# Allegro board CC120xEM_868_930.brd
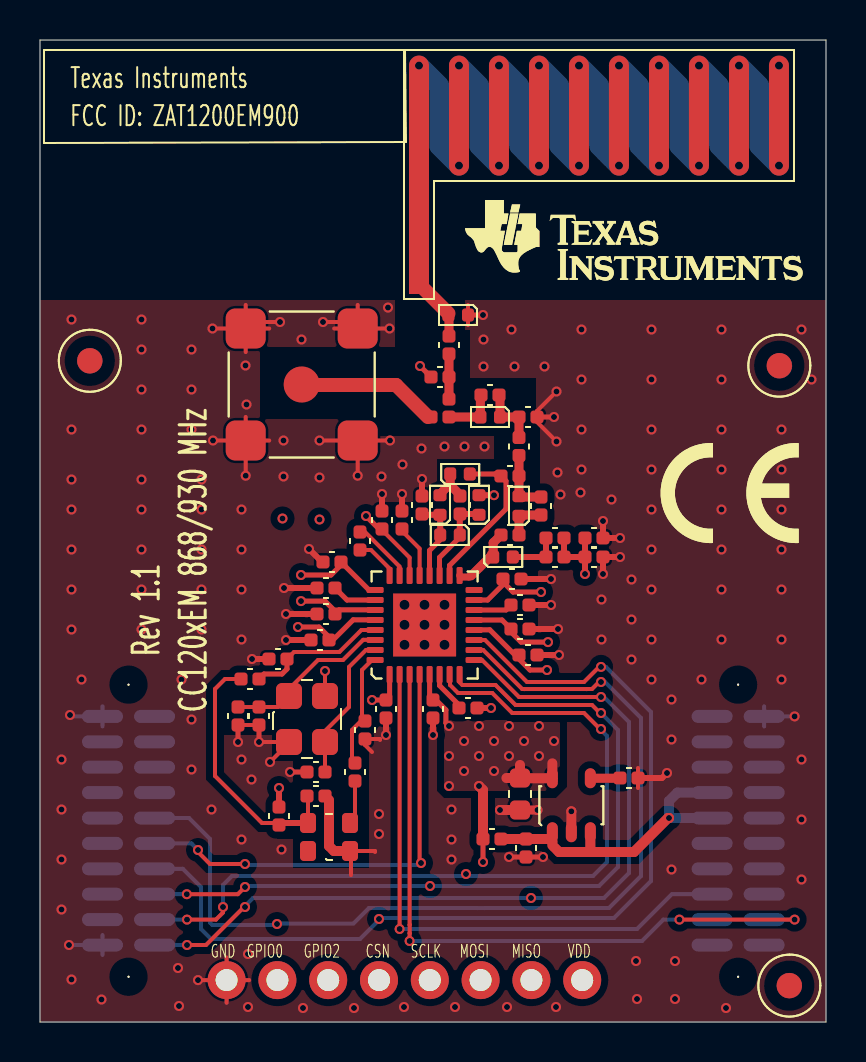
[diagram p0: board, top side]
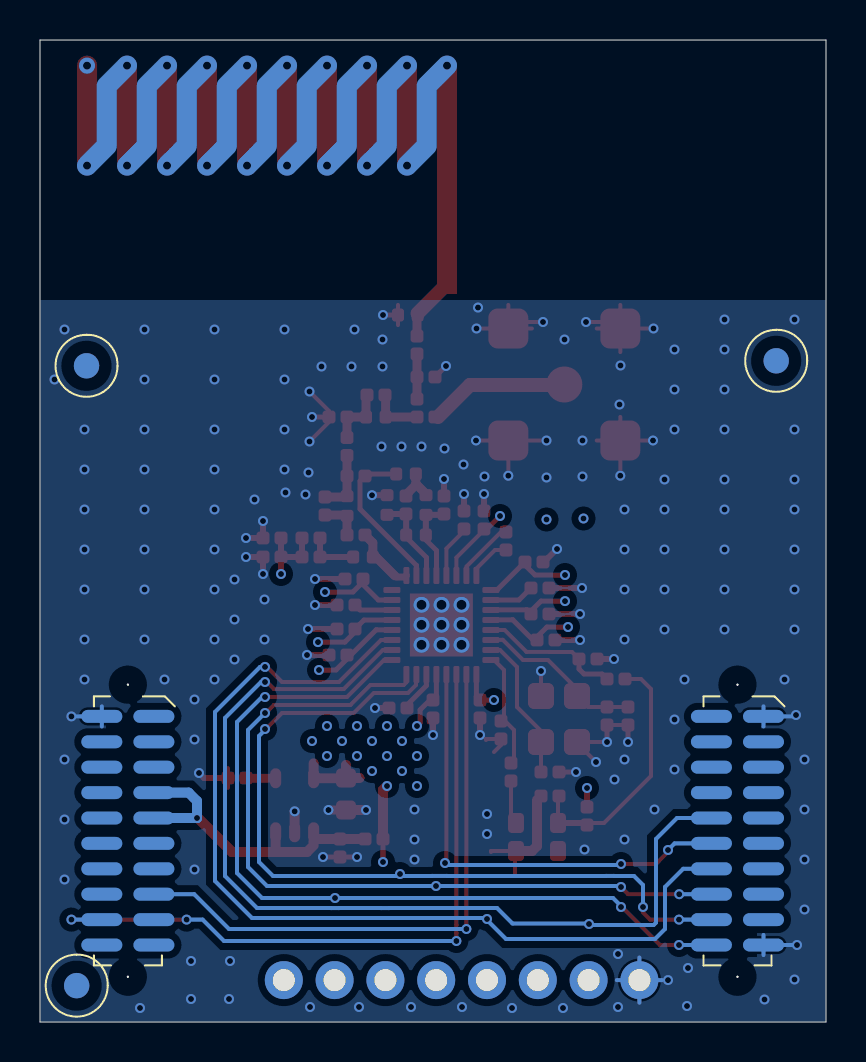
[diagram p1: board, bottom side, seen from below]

Outline 39.3 x 49.1 mm; copper layers: TOP, L2, L3, BOTTOM. Coordinates in mm from the lower left corner of the outline.
Outline path: 0,49.1 0,0 39.3,0 39.3,49.1 0,49.1

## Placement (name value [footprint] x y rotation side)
A1  ANTENNA  [ANTENNA868_915MHZ]  18.95 36.9 0 top
ANT1  DNM_0402  [CAPC1005X60N]  20.45 32.25 180 top
ANT2  1pF  [CAPC1005X60N]  20.45 33.4 90 top
ANT3  12nH  [IND_0402CSAN]  21.4 35.35 180 top
C11  47nF  [CAPC1005X60N]  17.3 16.1 270 top
C12  DNM_0402  [CAPC1005X60N]  24.3 9.15 270 top
C41  DNM_0402  [CAPC1005X60N]  29 12.2 0 top
C51  47nF  [CAPC1005X60N]  19.65 16.1 270 top
C52  2.2uF  [CAPC1608X90N]  24 12.2 270 top
C61  220nF  [CAPC1005X60N]  20.95 15.7 0 top
C121  47nF  [CAPC1005X60N]  24.85 18.35 180 top
C131  47nF  [CAPC1005X60N]  23.55 19.65 0 top
C151  47nF  [CAPC1005X60N]  23.15 22.15 0 top
C171  10nF  [CAPC1005X60N]  27.25 24.2 0 top
C172  100pF  [CAPC1005X60N]  27.25 23.25 0 top
C173  33pF  [CAPC1005X60N]  26.2 24.2 180 top
C174  15pF  [CAPC1005X60N]  23.05 24.35 0 top
C175  3pF  [CAPC1005X60N]  23.95 30.25 0 top
C176  1pF  [CAPC1005X60N]  25.05 25.35 90 top
C177  DNM_0402  [CAPC1005X60N]  22.95 31.35 180 top
C181  2.2pF  [CAPC1005X60N]  23.05 27.3 0 top
C191  3.3pF  [CAPC1005X60N]  21 25.4 90 top
C201  3.3pF  [CAPC1005X60N]  19.1 25.4 90 top
C211  10nF  [CAPC1005X60N]  18.1 24.65 90 top
C221  47nF  [CAPC1005X60N]  17.1 24.65 90 top
C231  1.5nF  [CAPC1005X60N]  16 23.6 90 top
C251  47nF  [CAPC1005X60N]  15.05 23 180 top
C261  47nF  [CAPC1005X60N]  14.75 21.7 180 top
C271  47nF  [CAPC1005X60N]  14.75 20.4 180 top
C281  47nF  [CAPC1005X60N]  14.45 19.1 180 top
C291  47nF  [CAPC1005X60N]  12.35 18.15 180 top
C301  15pF  [CAPC1005X60N]  10.95 15.75 270 top
C302  DNM_0402  [CAPC1005X60N]  9.9 15.75 270 top
C311  15pF  [CAPC1005X60N]  14.25 12.5 180 top
C321  DNM  [CAPC1005X60N]  14.25 11.3 180 top
C322  DNM  [CAPC1005X60N]  15.75 12.05 90 top
FIDU1  FIDU_1.27mm  [FID127X142]  37.47 1.82 0 top
FIDU2  FIDU_1.27mm  [FID127X142]  2.49 33.06 0 top
FIDU3  FIDU_1.27mm  [FID127X142]  36.97 32.81 0 top
FIDU4  FIDU_1.27mm  [FID127X142]  36.98 32.81 180 bottom
FIDU5  FIDU_1.27mm  [FID127X142]  37.47 1.82 180 bottom
FIDU6  FIDU_1.27mm  [FID127X142]  2.49 33.06 180 bottom
L1  BLM15HG102SN1  [INDC1005X60N]  23.05 9.15 180 top
L171  10nH  [IND_0402CSAN]  22.66 23.25 0 top
L172  7.5nH  [IND_0402CSAN]  23.95 25.31 90 top
L173  18nH  [INDC1005X60N]  23.95 28.32 90 top
L174  12nH  [IND_0402CSAN]  23 30.25 180 top
L191  15nH  [IND_0402CSAN]  20.99 24.35 180 top
L192  12nH  [IND_0402CSAN]  21.95 25.36 90 top
L193  12nH  [IND_0402CSAN]  20.51 27.4 0 top
L201  12nH  [IND_0402CSAN]  20 25.36 90 top
NOREF  -  []  -80.15 -110.9 0 top
P1  SFM-110-02-S-D-A-K-TR  [SAMTEC_SFM11002AN]  3.12 15.28 0 bottom
P2  SFM-110-02-S-D-A-K-TR  [SAMTEC_SFM11002AN]  33.61 15.28 0 bottom
P3  SMA-10V21-TGG  [HUSTSAN_SMA10V21TGGAN]  13.08 31.88 0 top
P4  CONN_8  [CON_1X8PAD_T1900CIR1100]  9.33 2.09 0 top
R12  0  [RESC1005X40N]  16.25 15.05 270 top
R141  56k  [RESC1005X40N]  23.55 20.85 0 top
R171  10  [RESC1005X40N]  25.3 23.25 0 top
R181  0  [RESC1005X40AN]  20.45 30.25 180 top
R321  DNM  [RESC1005X40N]  10.95 17.15 180 top
R322  DNM  [RESC1005X40N]  11.95 10.75 270 top
U2  TPS79330  [SOT95P280X145-5N]  25.62 9.49 0 top
U3  CC120xRHB  [QFNFC50P500X500X100-33BN]  17.48 17.38 0 top
UNK#REFDES  -  []  22.25 41.1 0 top
UNK#REFDES#2  -  []  33.65 23.95 0 top
X1  40MHz  [OSCCC250X320X80-4N]  12.45 16.3 270 top
X2  TG-5021CG  [OSCCC200X250X90-4BN]  13.4 8.55 0 top

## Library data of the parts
A1 = ANTENNA
ANT1 ANT2 C11 C12 C41 C51 C61 C121 C131 C151 C171 C172 C174-C177 C181 C191 C201 C211 C221 C231 C251 C261 C271 C281 C291 C301 C302 C311 = CAPACITOR: alternate symbols: (CAPC1005X60L,CAPC1005X60M)
ANT3 L171 L172 L174 L192 L193 L201 = INDUCTOR: alternate symbols: (IND_0402CSAM,IND_0402CSAL)
C52 = CAPACITOR: alternate symbols: (CAPC1608X90L,CAPC1608X90M)
C173 = CAPACITOR: alternate symbols: (CAPC1005X60M,CAPC1005X60L)
C321 C322 = CAPACITOR
FIDU1-FIDU6 = FIDMARK
L1 L191 = INDUCTOR
L173 = INDUCTOR: alternate symbols: (INDC1005X60L,INDC1005X60M)
P1 P2 = CONN_HEADER_2X10_P_S
P3 = CONN_COAX_1+4
P4 = CONN_HEADER_0
R12 R141 R321 R322 = RESISTOR
R171 = RESISTOR: alternate symbols: (RESC1005X40L,RESC1005X40M)
R181 = RESISTOR_3PORTS: alternate symbols: (RESC1005X40AL,RESC1005X40AM,RESC1005X40BL,RESC1005X40BM)
U2 = IC_PM_TPS79930_SOT5_0
U3 = IC_RF_CC1120_QFN32: alternate symbols: (QFNFC50P500X500X100-33BL,QFNFC50P500X500X100-33BM)
X1 = XTAL_4PIN_S: alternate symbols: (OSCCC250X320X80-4L,OSCCC250X320X80-4M)
X2 = XTAL_TG-5021CG

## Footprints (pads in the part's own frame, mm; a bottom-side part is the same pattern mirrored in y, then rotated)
ANTENNA868_915MHZ
  rect 1x1 smd: 1(0,0)
CAPC1005X60N
  custom 0.16x0.16 smd: 1(0,0) 2(0.9,0)
CAPC1608X90N
  custom 0.237x0.237 smd: 1(0,0) 2(1.6,0)
CON_1X8PAD_T1900CIR1100
  round 1.9 hole 1.1: 1(0,0) 2(2.54,0) 3(5.08,0) 4(7.62,0) 5(10.16,0) 6(12.7,0) 7(15.24,0) 8(17.78,0)
FID127X142
  round 1.27 smd: 1(0,0)
HUSTSAN_SMA10V21TGGAN
  round 1.8 smd: 1(0,0)
  custom 0.5x0.5 smd: 2(-2.8,-2.8) 3(2.8,-2.8) 4(2.8,2.8) 5(-2.8,2.8)
IND_0402CSAN
  custom 0.15x0.15 smd: 1(0,0) 2(0.98,0)
INDC1005X60N
  custom 0.16x0.16 smd: 1(0,0) 2(0.9,0)
OSCCC200X250X90-4BN
  custom 0.199x0.199 smd: 1(0,0) 2(2.1,0) 3(2.1,1.4) 4(0,1.4)
OSCCC250X320X80-4N
  custom 0.325x0.325 smd: 1(0,0) 2(2.3,0) 3(2.3,1.8) 4(0,1.8)
QFNFC50P500X500X100-33BN
  custom 0.075x0.075 smd: 1(0,0) 2(0.5,0) 3(1,0) 4(1.5,0) 5(2,0) 6(2.5,0) 7(3,0) 8(3.5,0) 9(4.225,0.725) 10(4.225,1.225) 11(4.225,1.725) 12(4.225,2.225) 13(4.225,2.725) 14(4.225,3.225) 15(4.225,3.725) 16(4.225,4.225) 17(3.5,4.95) 18(3,4.95) 19(2.5,4.95) 20(2,4.95) 21(1.5,4.95) 22(1,4.95) 23(0.5,4.95) 24(0,4.95) 25(-0.725,4.225) 26(-0.725,3.725) 27(-0.725,3.225) 28(-0.725,2.725) 29(-0.725,2.225) 30(-0.725,1.725) 31(-0.725,1.225) 32(-0.725,0.725)
  rect 3.15x3.15 smd: 33(1.75,2.475)
RESC1005X40AN
  custom 0.16x0.16 smd: 1(0,-0.9) 2(0,0) 3(0.9,0)
RESC1005X40N
  custom 0.16x0.16 smd: 1(0,0) 2(0.9,0)
SAMTEC_SFM11002AN
  round 0.1 hole 1.5 unplated: (1.302,-1.587) (1.302,13.018)
  oval 2.05x0.65 smd: 1(0,0) 2(2.603,0) 3(0,1.27) 4(2.603,1.27) 5(0,2.54) 6(2.603,2.54) 7(0,3.81) 8(2.603,3.81) 9(0,5.08) 10(2.603,5.08) 11(0,6.35) 12(2.603,6.35) 13(0,7.62) 14(2.603,7.62) 15(0,8.89) 16(2.603,8.89) 17(0,10.16) 18(2.603,10.16) 19(0,11.43) 20(2.603,11.43)
SOT95P280X145-5N
  oval 0.55x1 smd: 1(0,0) 2(0.95,0) 3(1.9,0) 4(1.9,2.7) 5(0,2.7)

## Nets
3V3A: C12.1 L1.1 P2.7 P2.9 U2.1(IN) U2.3(EN)
GND: ANT1.2 ANT3.1 C11.2 C12.2 C41.2 C51.2 C52.2 C61.2 C121.1 C131.2 C151.2 C171.2 C172.2 C175.2 C201.2 C211.2 C221.2 C251.2 C261.2 C271.2 C281.2 C291.2 C301.2 C302.2 C311.2 C321.1 L192.2 P1.1 P1.19 P2.2 P3.2 P3.3 P3.4 P3.5 P4.1 R12.2 R141.2 U2.2(GND) U3.33(EGP) X1.2 X1.4 X2.2(GND)
VDD_REG: C11.1 C51.1 C52.1 C121.2 C131.1 C151.1 C171.1 C172.1 C173.1 C221.1 C251.1 C271.1 C281.1 L1.2 P4.8 R171.2 R322.1 U2.5(OUT) U3.1(VDD_GUARD) U3.5(DVDD#5) U3.12(DVDD#12) U3.13(AVDD_IF) U3.15(AVDD_RF) U3.22(AVDD_SYNTH1) U3.25(AVDD_PFD_CHP) U3.27(AVDD_SYNTH2) U3.28(AVDD_XOSC)
CSN: P1.14 P4.4 U3.11(CS_N)
DCPL_XOSC: C291.1 R321.1 U3.29(DCPL_XOSC)
GPIO0: P1.10 P4.2 U3.10(GPIO0)
GPIO2: P1.12 P4.3 U3.4(GPIO2)
GPIO3: P2.18 U3.3(GPIO3)
MISO: P1.20 P4.7 U3.9(SO(GPIO1))
MOSI: P1.18 P4.6 U3.7(SI)
RESET: P2.15 U3.2(RESET_N)
SCLK: P1.16 P4.5 U3.8(SCLK)
N02751: C41.1 U2.4(NR)
N03028: C61.1 U3.6(DCPL)
N03080: C211.1 U3.21(DCPL_VCO)
N03171: C261.1 U3.26(DCPL_PFD_CHP)
N03297: C231.2 U3.23(LPF0)
N03301: C231.1 U3.24(LPF1)
N03775: C301.1 C302.1 U3.30(XOSC_Q1) X1.1
N03827: C311.1 U3.31(XOSC_X2) X1.3
N03987: C322.1 X2.3(OUT)
N04005: C322.2 R12.1 U3.32(EXT_OSC)
N04250: C321.2 R321.2 R322.2 X2.4(VCC)
N04524: R141.1 U3.14(RBIAS)
N06943: C191.1 L191.1 L192.1 U3.19(LNA_P)
N06950: C201.1 L191.2 L201.1 U3.20(LNA_N)
N06973: C191.2 L193.1 L201.2
N07362: C181.1 L193.2 U3.18(TRX_SW)
N07471: C174.1 L171.1 U3.17(PA)
N07475: C174.2 C176.1 L172.1
N07485: C176.2 C181.2 L172.2 L173.1
N07738: C175.1 C177.1 L173.2 L174.1
N07781: C177.2 L174.2 R181.2
N08395: C173.2 L171.2 R171.1
N35337: ANT1.1 ANT2.1 R181.1
N35679: A1.1(FEED/GND_1) ANT2.2 ANT3.2
N41911: P3.1 R181.3

Pads without a net: FIDU1 1; FIDU2 1; FIDU3 1; FIDU4 1; FIDU5 1; FIDU6 1; P1 2 3 4 5 6 7 8 9 11 13 15 17; P2 1 3 4 5 6 8 10 11 12 13 14 16 17 19 20; U3 16; X2 1

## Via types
v1: diameter 0.8, hole 0.4, TOP to BOTTOM, 19 vias
v2: diameter 0.5, hole 0.3, TOP to BOTTOM, 229 vias
v3: diameter 0.8, hole 0.5, TOP to BOTTOM, 9 vias

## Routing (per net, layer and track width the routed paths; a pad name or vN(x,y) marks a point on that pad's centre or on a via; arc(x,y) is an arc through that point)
3V3A: length 16.3
  TOP w0.2: 25.62,8.83 25.62,9 ; 27.52,8.52 27.5,8.5
  TOP w0.5: U2.3 27.52,8.52 ; L1.1 C12.1 25.47,9.15 25.62,9 U2.1 ; v2(31.45,10.2) 31.4,10.2 29.7,8.5 25.95,8.5 25.62,8.83
  BOTTOM w0.5: P2.9 v2(31.45,10.2) 31.45,11.05 31.87,11.47 P2.7
GND: length 100.1
  TOP w0.2: P4.1 9.33,3.22 ; P4.1 v2(7.9,2.09) ; P4.1 10.46,2.09 ; P4.1 9.33,0.97 ; 15.88,34.67 15.88,35.85 ; 15.88,34.67 15.56,35 v2(14.15,35) ; 15.88,34.67 14.71,34.67 ; 15.88,34.67 v2(17.47,34.67) ; 16.75,8.5 16.75,8.55 15.55,8.55 ; 29.9,11.7 C41.2 29.9,12.7 ; P3.2 10.29,30.25 ; P3.2 v2(8.65,29.07) ; P3.2 11.46,29.07 ; P3.2 v2(10.29,27.31) ; 15.88,29.07 v2(15.88,27.31) ; 15.88,29.07 v2(17.5,29.07) ; 15.88,29.07 v2(13.97,29.07) ; 21.4,35.85 ANT3.1 21.4,34.85 ; v2(25.82,31.52) 24.85,30.55 C175.2 24.85,30 v2(25.82,29.02) ; P3.5 11.46,34.67 ; P3.5 10.29,33.5 ; P3.5 10.61,35 v2(12,35) ; P3.5 v2(8.62,34.67) ; P3.5 10.29,35.85 ; 16.6,13.5 16.25,13.85 R12.2 17,14.15 17,14.1 ; v2(10.95,14) X1.2 12.45,13.95 v2(11.5,13) ; 15.55,8.55 15.55,7.35 ; 15.55,8.55 X2.2 ; X1.4 v2(14.25,17.55) ; C302.2 C301.2
  TOP w0.25: C321.1 14.45,11.1 ; C311.2 v2(12.5,12.5) ; C175.2 v2(25.7,30.25) ; ANT3.1 v2(22.15,35.35) ; C302.2 v2(9.9,14) ; v2(23.45,8.25) C12.2 v2(25.15,8.25) ; ANT1.2 v2(19,32.8) ; C301.2 v2(10.95,14)
  TOP w0.3: C281.2 v2(12.3,19.1) ; C221.2 v2(17.1,26.4) ; C211.2 v2(18.1,26.4) ; R141.2 v2(25.55,20.85) ; C251.2 14.1,23 v2(13.45,23.65) ; C271.2 v2(12.3,20.4) ; L192.2 v2(22.7,26.34) ; v2(31.35,12.45) 31.1,12.2 C41.2 ; v2(29,24.2) C171.2 v2(28.15,25.05) ; C61.2 v2(22.55,15.7) ; C11.2 v2(17.3,14.35) ; v2(29,23.25) C172.2 v2(28.15,22.4) ; C261.2 v2(12.2,21.7) ; C131.2 v2(25.9,19.65) ; C201.2 v2(19.1,27.15) ; C291.2 v2(10.6,18.15) ; C121.1 v2(25.95,18.35) ; C151.2 v2(25.55,22.15) ; C51.2 v2(19.65,14.35)
  TOP w0.45: C52.2 v2(24.88,10.6)
  TOP w0.5: U2.2 v2(26.57,10.53) ; C52.2 v2(23,10.6) ; 14.45,11.1 14.45,8.8 14.7,8.55 X2.2
  L2 w0.2: 8.2,2.09 P4.1 ; P4.1 9.33,0.97 ; P4.1 10.46,2.09 ; P4.1 9.33,3.22
  L3 w0.2: 8.2,2.09 P4.1 ; P4.1 9.33,0.97 ; P4.1 10.46,2.09 ; P4.1 9.33,3.22
  BOTTOM w0.2: P1.19 v2(1.45,3.85) ; P1.19 3.12,3.35 ; P1.19 3.12,4.35 ; 36.21,14.78 P2.2 ; P2.2 36.21,15.78 ; P2.2 v2(37.73,15.28) ; 8.2,2.09 P4.1 ; P4.1 9.33,0.97 ; P4.1 10.46,2.09 ; P4.1 9.33,3.22 ; 3.12,14.78 P1.1 ; P1.1 3.12,15.78 ; P1.1 1.57,15.28 v2(1.5,15.35)
  vias: v2(1.07,13.12) v2(1.07,10.62) v2(1.07,8.12) v2(1.07,5.62) v2(1.57,35.12) v2(1.57,29.62) v2(1.57,27.12) v2(1.57,25.62) v2(1.57,23.62) v2(1.57,21.62) v2(1.57,19.62) v2(1.57,2.12) v2(2.08,17.12) v2(3.08,1.12) v2(5.08,35.12) v2(5.08,33.62) v2(5.08,31.62) v2(5.08,29.62) v2(5.08,27.12) v2(5.08,25.62) v2(5.08,23.62) v2(5.08,21.62) v2(5.08,19.62) v2(6.9,2.7) v2(6.95,0.8) v2(7.08,17.12) v2(7.58,33.62) v2(7.58,31.62) v2(7.58,29.62) v2(7.58,15.12) v2(7.58,12.62) v2(8.07,27.12) v2(8.07,25.62) v2(8.07,23.62) v2(8.07,21.62) v2(8.07,19.62) v2(8.57,10.62) v2(10.07,25.62) v2(10.07,23.62) v2(10.07,21.62) v2(10.07,19.12) v2(10.07,13.12) v2(10.07,9.12) v2(10.27,32.82) v2(10.32,30.88) v2(10.4,3.4) v2(10.4,0.75) v2(10.57,12.12) v2(12.07,8.62) v2(12.17,29.07) v2(12.17,27.27) v2(13.07,34.12) v2(13.15,0.7) v2(13.97,27.22) v2(15.7,0.7) v2(16.95,10.4) v2(16.95,9.4) v2(17.07,27.27) v2(17.4,35.72) v2(18.12,27.88) v2(18.2,0.75) v2(19.07,28.67) v2(20.22,28.77) v2(20.57,10.62) v2(20.57,9.12) v2(20.57,8.12) v2(20.75,0.75) v2(21.22,28.77) v2(22.18,34.12) v2(22.18,32.77) v2(22.22,28.77) v2(23.35,0.75) v2(23.57,34.62) v2(23.72,32.77) v2(25.22,32.77) v2(25.88,27.47) v2(25.8,0.75) v2(26.02,26.38) v2(27.07,34.62) v2(27.07,32.12) v2(27.07,29.62) v2(27.07,27.62) v2(27.02,26.47) v2(28.07,21.12) v2(28.07,19.12) v2(28.57,26.12) v2(29.57,22.12) v2(29.57,20.12) v2(29.57,18.12) v2(29.8,3.05) v2(29.85,1.15) v2(30.57,34.62) v2(30.57,32.12) v2(30.57,29.62) v2(30.57,27.62) v2(30.57,25.62) v2(30.57,23.62) v2(30.57,21.62) v2(30.57,19.12) v2(30.57,17.12) v2(31.57,16.12) v2(31.57,14.12) v2(31.57,7.62) v2(31.75,3.05) v2(31.75,1.15) v2(33.08,17.12) v2(34.08,34.62) v2(34.08,32.12) v2(34.08,29.62) v2(34.08,27.62) v2(34.08,25.62) v2(34.08,23.62) v2(34.08,21.62) v2(34.08,19.12) v2(34.3,0.7) v2(37.08,29.62) v2(37.08,27.62) v2(37.08,25.62) v2(37.08,23.62) v2(37.08,21.62) v2(37.08,19.12) v2(37.08,17.12) v2(38.08,34.62) v2(38.08,13.12) v2(38.08,10.12) v2(38.08,7.12) v2(38.58,32.12) v3(18.22,20.86) v3(18.22,19.86) v3(18.22,18.86) v3(19.22,20.86) v3(19.22,19.86) v3(19.22,18.86) v3(20.22,20.86) v3(20.22,19.86) v3(20.22,18.86)
VDD_REG: length 56.7
  TOP w0.2: 16.75,20.61 U3.27 ; 17.48,16.28 17.47,16.27 ; U3.22 18.48,23.22 17.1,24.6 C221.1
  TOP w0.25: v2(12.9,19.75) 13.95,19.75 14.45,19.25 C281.1 14.65,19.1 15.66,20.11 16.75,20.11 U3.28 ; U3.13 23.1,20.1 C131.1 ; U3.25 16.45,21.6 C251.1 15.05,22.85 14.55,22.35 v2(13.05,22.35) ; C131.1 23.55,19.5 24.05,18.99 v2(25.4,18.99) ; C131.1 23.5,19.65 ; v2(22.15,8) L1.2 ; U3.1 17.48,16.28 ; U3.15 22.38,21.1 23.15,21.87 23.15,22 ; U3.12 21.71,19.61 22.49,19.61 23.75,18.35 C121.2 23.95,18.15 24.5,17.6 v2(25.35,17.6) ; U3.5 19.48,16.27 C51.1 19.8,16.1 20.29,15.61 20.29,14.96 v2(20.45,14.8) ; 16.75,20.61 14.96,20.61 C271.1 14.75,20.54 14.25,21.04 v2(13.05,21.04) ; 23.15,22 C151.1 ; 23.15,22 23.65,21.5 v2(25.05,21.5) ; v2(16.6,16.1) C11.1 17.47,16.27 ; v2(16.3,25.3) 16.95,24.65 C221.1
  TOP w0.3: C172.1 C171.1 ; C172.1 v2(27.25,22.4) ; C172.1 R171.2 C173.1 ; R322.1 v2(11.95,11.7)
  TOP w0.5: C52.1 23.32,12.2 ; C52.1 24.01,12.19 U2.5 25.62,12.93 ; C52.1 24,12.85 ; L1.2 22.15,11.6 v2(21.95,11.8)
  L3 w0.25: P4.8 27.11,4.59 24.4,7.3 22.85,7.3 v2(22.15,8)
  vias: v2(12.12,25.17) v2(13.97,25.12) v2(20.45,13.3) v2(20.45,11.8) v2(21.2,14.05) v2(21.2,12.55) v2(21.95,14.8) v2(21.95,13.3) v2(22.7,14.05) v2(22.7,12.55) v2(23.45,14.8) v2(23.45,13.3) v2(24.2,14.05) v2(24.95,14.8) v2(24.95,13.3) v2(25.7,14.05)
CSN: length 51.2
  TOP w0.2: v2(28.05,17.75) 27.95,17.75 27.2,17 24.35,17 22.25,19.1 U3.11
  L3 w0.2: P4.4 v2(16.95,5.15)
  BOTTOM w0.2: v2(28.05,17.75) 28.05,17.75 28.3,17.75 30.55,15.5 30.55,7.05 28.7,5.2 17,5.2 v2(16.95,5.15) 16.9,5.1 16.9,5.05 16,4.15 8.55,4.15 8.05,4.65 8.05,6.75 7.14,7.66 P1.14
DCPL_XOSC: length 7.1
  TOP w0.2: C291.1 12.7,18.5 13.8,18.5 13.8,18.5 14.97,18.5 16.07,19.6 U3.29
  TOP w0.25: C291.1 12.35,17.65 12.1,17.4 11.2,17.4 R321.1
GPIO0: length 50.9
  TOP w0.2: v2(28.05,17) 27.95,17 27.6,16.65 27.35,16.65 27.35,16.65 24.2,16.65 24.2,16.65 24.11,16.65 22.16,18.6 U3.10
  L3 w0.2: P4.2 11.87,4.88 v2(11.85,4.9)
  BOTTOM w0.2: P1.10 7.45,10.2 8.5,9.15 8.5,4.97 8.62,4.85 11.8,4.85 v2(11.85,4.9) 11.77,4.9 11.8,4.93 15.67,4.93 16.45,5.7 21.84,5.7 21.84,5.7 22.26,5.7 22.26,5.7 24.34,5.7 24.34,5.7 24.76,5.7 24.76,5.7 28.45,5.7 30.05,7.3 30.05,15.2 28.25,17 v2(28.05,17)
GPIO2: length 30.9
  TOP w0.2: v2(19.05,7.95) 18.98,8.02 U3.4 ; v2(10.25,7.9) 8.5,7.9 7.9,8.5 v2(7.9,8.6)
  L3 w0.2: v2(10.25,7.9) 10.4,7.9 14.41,3.89 P4.3
  BOTTOM w0.2: v2(10.25,7.9) 10.3,7.85 18.95,7.85 v2(19.05,7.95) ; P1.12 7.57,8.93 v2(7.9,8.6)
GPIO3: length 34.5
  TOP w0.2: v2(18.48,4.05) 18.48,4.44 18.48,4.44 18.48,4.86 18.48,4.86 U3.3 ; v2(31.97,5.12) v2(37.73,5.12)
  BOTTOM w0.2: v2(31.97,5.12) 31.17,5.12 30.1,4.05 v2(18.48,4.05) ; v2(37.73,5.12) P2.18
MISO: length 45.9
  TOP w0.2: v2(28.05,16.25) 23.95,16.25 22.1,18.1 U3.9 ; v2(7.35,3.85) 8.3,3.85 10.2,5.75 v2(10.25,5.75)
  L3 w0.2: P4.7 24.57,6.18 v2(24.55,6.2)
  BOTTOM w0.2: v2(10.25,5.75) 10.25,5.8 10.65,6.2 v2(24.55,6.2) 28.2,6.2 29.45,7.45 29.45,15 28.2,16.25 v2(28.05,16.25) ; P1.20 v2(7.35,3.85)
MOSI: length 46.1
  TOP w0.2: v2(7.35,5.12) 8.8,5.12 9.15,5.47 v2(9.15,5.75) ; U3.7 20.5,17.35 20.5,16.85 20.9,16.45 22.61,16.45 23.61,15.45 27.2,15.45 28,14.65 v2(28.05,14.65)
  L3 w0.2: v2(21.3,7.4) 22.03,6.67 P4.6
  BOTTOM w0.2: v2(28.05,14.65) 28.05,14.6 28.35,14.3 28.35,8 27.65,7.3 21.4,7.3 v2(21.3,7.4) 21.2,7.3 19.71,7.3 19.71,7.3 18.94,7.3 18.94,7.3 11.01,7.3 11.01,7.3 10.59,7.3 10.59,7.3 9.6,7.3 9.15,6.85 v2(9.15,5.75) ; P1.18 v2(7.35,5.12)
Net_4:
  vias: v1(20.95,47.82) v1(22.95,42.82)
Net_5:
  vias: v1(22.95,47.82) v1(24.95,42.82)
Net_6:
  vias: v1(24.95,47.82) v1(26.95,42.82)
Net_7:
  vias: v1(26.95,47.82) v1(28.95,42.82)
Net_8:
  vias: v1(28.95,47.82) v1(30.95,42.82)
Net_9:
  vias: v1(30.95,47.82) v1(32.95,42.82)
Net_10:
  vias: v1(32.95,47.82) v1(34.95,42.82)
Net_11:
  vias: v1(34.95,47.82) v1(36.95,47.82) v1(36.95,42.82)
Net_12:
  vias: v1(18.95,47.82) v1(20.95,42.82)
RESET: length 29.1
  TOP w0.2: U3.2 v2(17.98,4.65)
  BOTTOM w0.2: v2(17.98,4.65) 29.85,4.65 31.59,6.39 P2.15
SCLK: length 44.8
  TOP w0.2: U3.8 20.98,16.99 21.12,16.85 22.78,16.85 23.78,15.85 27.6,15.85 28,15.45 v2(28.05,15.45) ; v2(7.34,6.39) 9.89,6.39 v2(10.25,6.75)
  L3 w0.2: P4.5 19.49,6.79 v2(19.5,6.8)
  BOTTOM w0.2: v2(28.05,15.45) 28.9,14.6 28.9,7.75 27.95,6.8 19.72,6.8 19.72,6.8 19.3,6.8 19.3,6.8 ; 19.3,6.8 10.3,6.8 v2(10.25,6.75) ; 19.3,6.8 v2(19.5,6.8) ; P1.16 v2(7.34,6.39)
N02751: length 1.5
  TOP w0.45: C41.1 28.99,12.19 U2.4
N03028: length 2.1
  TOP w0.2: 19.98,16.83 19.97,16.82
  TOP w0.25: C61.1 20.95,15.85 19.97,16.82 ; U3.6 19.98,16.83
N03080: length 2.7
  TOP w0.2: C211.1 18.1,24.55 18.98,23.67 U3.21
N03171: length 2.3
  TOP w0.25: C261.1 15.35,21.1 U3.26
N03297: length 3.2
  TOP w0.2: U3.23 17.98,22.28 17.97,22.29 17.97,22.77 16.25,24.5 C231.2
N03301: length 2.3
  TOP w0.2: U3.24 17.48,22.27 17.47,22.27 17.47,22.67 16.55,23.6 C231.1
N03775: length 8.6
  TOP w0.2: U3.30 16.75,19.11 16.16,19.11 15.15,18.1 13.9,18.1 12.45,16.65 ; 12.45,16.65 X1.1 11.9,15.75 C301.1 C302.1 ; 12.45,16.65 12.38,16.57
N03827: length 7.4
  TOP w0.2: C311.1 X1.3 14.25,14.55 15.45,15.75 15.45,17.75 16.3,18.6 U3.31
N03987: length 2.2
  TOP w0.2: C322.1 15.75,10.2 X2.3
N04005: length 6
  TOP w0.2: U3.32 16.6,18.1 16.1,17.6 16.1,16.31 16.1,16.31 16.1,15.89 16.1,15.89 16.1,15.2 R12.1 16.05,15.05 15.6,14.6 15.6,13.1 C322.2
N04250: length 12.9
  TOP w0.2: X2.4 13.4,11.25 C321.2 ; 12.05,9.95 R322.2 11.85,9.95 11.1,9.95 8.75,12.3 8.75,16.65 9.25,17.15 R321.2
  TOP w0.3: X2.4 12.05,9.95
N04524: length 1.9
  TOP w0.2: 23.3,20.6 23.31,20.61
  TOP w0.25: 23.31,20.61 R141.1 ; U3.14 23.3,20.6
N06943: length 4.5
  TOP w0.25: L191.1 20.99,24.24 19.97,23.22 19.97,22.33 U3.19
  TOP w0.3: L192.1 21.91,25.4 C191.1 20.99,25.39 L191.1
N06950: length 4.2
  TOP w0.25: L191.2 20,24.34 20,24.1 19.47,23.57 19.47,22.33 U3.20
  TOP w0.3: C201.1 19.14,25.36 L201.1 20.01,25.35 L191.2
N06973: length 2.1
  TOP w0.45: 20.51,26.85 L193.1 ; 20.51,26.85 21,26.36 C191.2 ; 20.51,26.85 20.45,26.85 20,26.4 L201.2
N07362: length 7.9
  TOP w0.25: U3.18 20.48,22.82 20.47,22.82 23.3,25.65 23.3,27.05 C181.1 22.85,27.3 22.75,27.4 L193.2
N07471: length 3.4
  TOP w0.35: U3.17 21.05,22.25 21.46,22.25 21.52,22.31 21.56,22.31
  TOP w0.45: C174.1 22.66,23.96 L171.1 22.5,23.25 21.56,22.31
N07475: length 2.1
  TOP w0.45: C176.1 23.99,25.35 L172.1 C174.2
N07485: length 3.2
  TOP w0.2: L173.1 23.95,28.29
  TOP w0.45: C176.2 23.99,26.25 L172.2 C181.2 23.95,28.29 23.96,28.3
N07738: length 3.1
  TOP w0.2: 23,31.3 C177.1
  TOP w0.45: L173.2 C175.1 L174.1 23,31.3
N07781: length 2.7
  TOP w0.2: 22.02,31.32 C177.2
  TOP w0.45: R181.2 L174.2 22.02,31.32
N08395: length 2.6
  TOP w0.3: C173.2 R171.1 L171.2
N35337: length 2.2
  TOP w0.45: ANT2.1 ANT1.1 R181.1
N35679: length 3.2
  TOP w0.2: 20.45,35.32 ANT3.2 20.42,35.43
  TOP w0.45: ANT2.2 20.45,35.32
  TOP w0.7: A1.1 20.42,35.43
N41911: length 7.1
  TOP w0.2: P3.1 13.11,31.85
  TOP w0.45: 19.4,30.25 R181.3
  TOP w0.7: 19.4,30.25 17.8,31.85 13.11,31.85

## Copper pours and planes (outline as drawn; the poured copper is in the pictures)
GND on TOP: 0.02,0.02 0.02,36.1 17.75,36.1 17.75,33.75 11,33.75 11,30.15 16.8,30.15 16.8,29.3 22.7,29.3 22.7,28.15 19.85,28.15 19.85,26.7 21.75,26.7 21.75,25.1 23.1,25.1 23.1,26.45 24.8,26.45 24.8,26.75 25,26.75 25,29.8 24.8,29.8 24.8,32.2 21.5,32.2 21.5,34.6 21.25,34.6 21.25,36.1 39.28,36.1 39.28,0.02 ; 5 cut-outs
GND on BOTTOM: 0.02,0.02 0.02,36.1 39.28,36.1 39.28,0.02 ; 5 cut-outs
GND on L2: 0.02,0.02 0.02,36.1 39.28,36.1 39.28,0.02
GND on L3: 0.02,0.02 0.02,36.1 39.28,36.1 39.28,0.02 ; 5 cut-outs
VDD_REG on TOP: 26,11.9 25.65,11.55 20.35,11.55 20.2,11.7 20.2,14.95 20.35,15.1 25.85,15.1 26,14.95
VDD_REG on L3: 27.75,25.8 27.75,11.2 11.35,11.2 11.35,25.8
Net_4 on BOTTOM (solid shape): 20.6,47.47 20.6,48.17 21.3,48.17 22.32,47.16 22.42,47 22.46,46.81 22.46,44.01 23.3,43.17 23.3,42.47 22.59,42.47 21.61,43.45 21.5,43.61 21.46,43.81 21.46,46.6
Net_5 on BOTTOM (solid shape): 22.59,47.47 22.59,48.17 23.3,48.17 24.31,47.16 24.42,47 24.46,46.81 24.46,44.01 25.3,43.17 25.3,42.47 24.59,42.47 23.61,43.45 23.5,43.61 23.46,43.81 23.46,46.6
Net_6 on BOTTOM (solid shape): 24.6,47.47 24.6,48.17 25.3,48.17 26.32,47.16 26.42,47 26.46,46.81 26.46,44.01 27.3,43.17 27.3,42.47 26.59,42.47 25.61,43.45 25.5,43.61 25.46,43.81 25.46,46.6
Net_7 on BOTTOM (solid shape): 26.59,47.47 26.59,48.17 27.3,48.17 28.32,47.16 28.42,47 28.46,46.81 28.46,44.01 29.3,43.17 29.3,42.47 28.59,42.47 27.61,43.45 27.5,43.61 27.46,43.81 27.46,46.6
Net_8 on BOTTOM (solid shape): 28.59,47.47 28.59,48.17 29.3,48.17 30.31,47.16 30.42,47 30.46,46.81 30.46,44.01 31.3,43.17 31.3,42.47 30.59,42.47 29.61,43.45 29.5,43.61 29.46,43.81 29.46,46.6
Net_9 on BOTTOM (solid shape): 30.6,47.47 30.6,48.17 31.3,48.17 32.32,47.16 32.42,47 32.46,46.81 32.46,44.01 33.3,43.17 33.3,42.47 32.59,42.47 31.61,43.45 31.5,43.61 31.46,43.81 31.46,46.6
Net_10 on BOTTOM (solid shape): 32.59,47.47 32.59,48.17 33.3,48.17 34.32,47.16 34.42,47 34.46,46.81 34.46,44.01 35.3,43.17 35.3,42.47 34.59,42.47 33.61,43.45 33.5,43.61 33.46,43.81 33.46,46.6
Net_11 on BOTTOM (solid shape): 34.6,47.47 34.6,48.17 35.3,48.17 36.32,47.16 36.42,47 36.46,46.81 36.46,44.01 37.3,43.17 37.3,42.47 36.59,42.47 35.61,43.45 35.5,43.61 35.46,43.81 35.46,46.6
Net_12 on BOTTOM (solid shape): 18.6,47.47 18.6,48.17 19.3,48.17 20.32,47.16 20.43,47 20.46,46.81 20.46,44.01 21.3,43.17 21.3,42.47 20.6,42.47 19.61,43.45 19.5,43.61 19.46,43.81 19.46,46.6

Small or netless copper shapes (teardrops, artwork), in the pictures only: 10 on TOP

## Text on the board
Package Geometry/Pastemask Bottom: SP4 | 11
User.Comments: PL4 | 7
Ref Des/Assembly Top: CC120xEM 868/930 MHz
Package Geometry/Pastemask Top: SP1 | 10
Ref Des/Silkscreen Top: GND | GPIO0 | GPIO2 | CSN | SCLK | MOSI | MISO | VDD | Texas Instruments | FCC ID: ZAT1200EM900 | Rev 1.1 | CC120xEM 868/930 MHz
NCLEGEND-1-4: FIGURE | SIZE | 0.3 | 0.5 | 1.5001 | DRILL CHART: TOP to BOTTOM | ALL UNITS ARE IN MILLIMETERS | PLATED | NON-PLATED | QTY | 222 | 9 | 4
